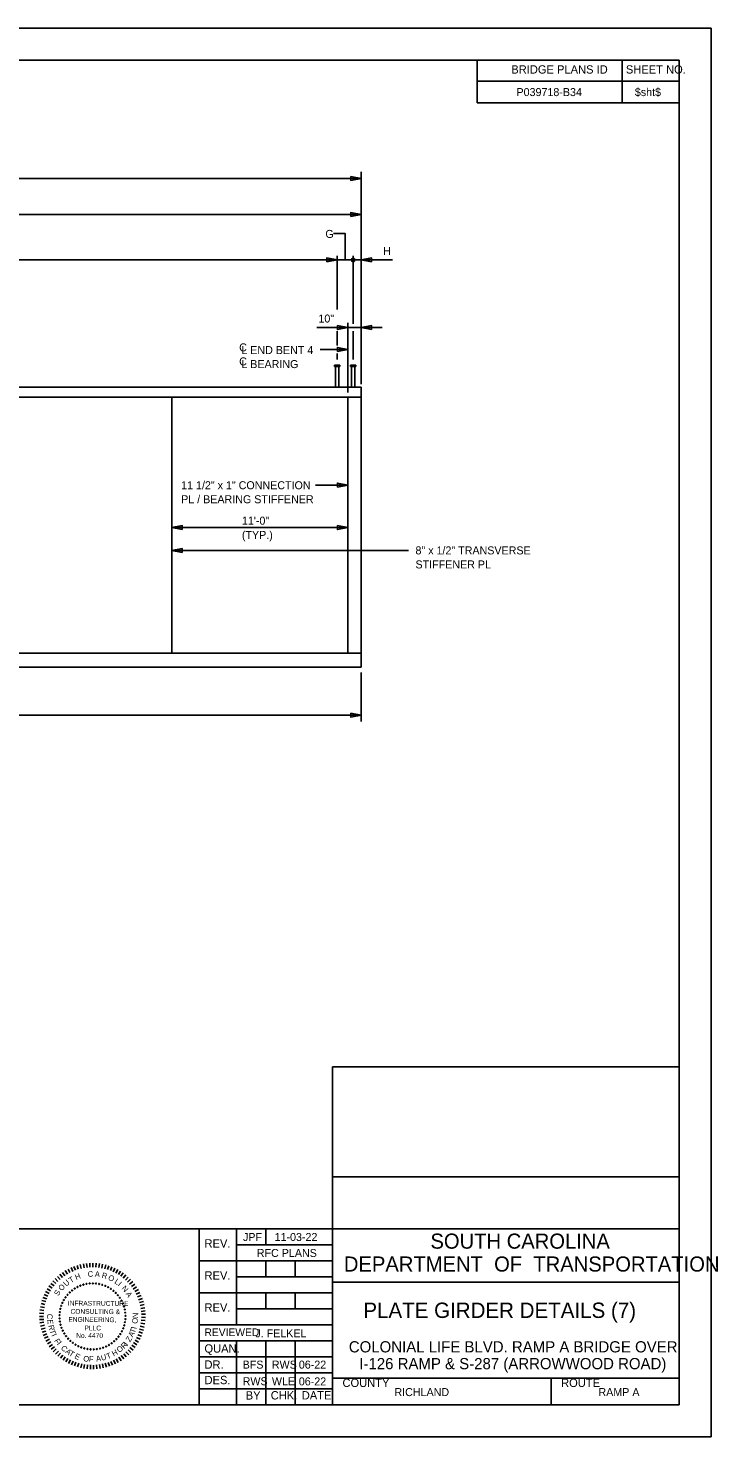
# Model space of a CAD drawing. Extents: x -383 to -161, y -356 to -99.
# Drawn here: x -203.9 to -160.8, y -187.5 to -99.5 of the extents above; entities that cross this region are included whole.
import ezdxf

# ---------------------------------------------------------------- set-up
doc = ezdxf.new("R2010")
doc.units = 0
for name, color, linetype in [('BR_AUTO DIMENSION', 7, 'Continuous'), ('BR_BORDER LINES', 7, 'Continuous'), ('BR_CENTER LINES', 7, 'Continuous'), ('BR_STRUCTURAL STEEL', 7, 'Continuous'), ('BR_TEXT', 7, 'Continuous'), ('Default', 7, 'Continuous'), ('Level 31', 7, 'Continuous')]:
    doc.layers.add(name, color=color, linetype=linetype)

msp = doc.modelspace()

# ---------------------------------------------------------------- linework, layer by layer
at = {"layer": 'BR_AUTO DIMENSION'}
for p, q in [((-278.644, -108.876), (-183.048, -108.876)), ((-183.048, -121.718), (-183.048, -108.463)), ((-278.644, -111.134), (-183.048, -111.134)), ((-184.548, -113.971), (-277.144, -113.971)), ((-184.548, -117.054), (-184.548, -113.71)), ((-181.095, -113.971), (-184.548, -113.971)), ((-183.548, -117.968), (-183.548, -113.71)), ((-185.813, -118.196), (-181.742, -118.196)), ((-184.548, -119.304), (-184.548, -118.423)), ((-183.548, -120.185), (-183.548, -118.423)), ((-183.882, -119.558), (-185.605, -119.558)), ((-184.548, -120.185), (-184.548, -119.822)), ((-183.882, -128.037), (-185.899, -128.037)), ((-194.882, -130.686), (-183.882, -130.686)), ((-194.882, -132.128), (-180.084, -132.128)), ((-183.048, -139.746), (-183.048, -142.798)), ((-278.644, -142.397), (-183.048, -142.397))]:
    msp.add_line(p, q, dxfattribs=at)
for points in [[(-183.698, -108.751), (-183.048, -108.876), (-183.698, -109.001)], [(-183.698, -111.259), (-183.048, -111.134), (-183.698, -111.009)], [(-185.198, -114.096), (-184.548, -113.971), (-185.198, -113.846)], [(-182.398, -114.096), (-183.048, -113.971), (-182.398, -113.846)], [(-184.532, -118.071), (-183.882, -118.196), (-184.532, -118.321)], [(-182.398, -118.321), (-183.048, -118.196), (-182.398, -118.071)], [(-184.532, -119.683), (-183.882, -119.558), (-184.532, -119.433)], [(-184.532, -128.162), (-183.882, -128.037), (-184.532, -127.912)], [(-194.232, -130.811), (-194.882, -130.686), (-194.232, -130.561)], [(-184.532, -130.561), (-183.882, -130.686), (-184.532, -130.811)], [(-194.232, -132.253), (-194.882, -132.128), (-194.232, -132.003)], [(-183.698, -142.272), (-183.048, -142.397), (-183.698, -142.522)]]:
    msp.add_lwpolyline(points, close=True, dxfattribs=at)
msp.add_lwpolyline([(-184.048, -113.971), (-184.048, -112.325), (-184.788, -112.325)], dxfattribs=at)
msp.add_circle((-183.548, -113.971), 0.111, dxfattribs=at)
at = {"layer": 'BR_BORDER LINES'}
for p, q in [((-163.178, -101.489), (-297.843, -101.489)), ((-175.788, -104.156), (-175.788, -101.489)), ((-166.722, -104.156), (-166.722, -101.489)), ((-163.178, -185.489), (-163.178, -101.489)), ((-175.788, -102.808), (-163.178, -102.808)), ((-166.722, -102.808), (-163.178, -102.808)), ((-163.178, -104.156), (-175.788, -104.156)), ((-184.846, -185.489), (-184.846, -164.383)), ((-184.846, -164.383), (-163.178, -164.383)), ((-184.845, -171.242), (-163.178, -171.242)), ((-214.64, -174.489), (-193.18, -174.489)), ((-193.18, -185.489), (-193.18, -174.489)), ((-193.18, -174.489), (-163.178, -174.489)), ((-190.846, -174.489), (-190.846, -180.489)), ((-189.013, -175.489), (-189.013, -174.489)), ((-190.846, -175.489), (-184.846, -175.489)), ((-193.18, -176.489), (-184.846, -176.489)), ((-189.013, -177.489), (-189.013, -176.489)), ((-187.179, -177.489), (-187.179, -176.489)), ((-190.846, -177.489), (-184.846, -177.489)), ((-193.18, -178.489), (-184.846, -178.489)), ((-189.013, -179.489), (-189.013, -178.489)), ((-187.179, -179.489), (-187.179, -178.489)), ((-184.846, -177.822), (-184.846, -177.822)), ((-184.846, -177.823), (-163.178, -177.823)), ((-190.846, -179.489), (-184.846, -179.489)), ((-193.18, -180.489), (-184.846, -180.489)), ((-193.18, -181.489), (-184.846, -181.489)), ((-190.846, -181.489), (-190.846, -185.489)), ((-189.013, -181.489), (-189.013, -185.489)), ((-187.179, -181.489), (-187.179, -185.489)), ((-193.18, -182.489), (-184.846, -182.489)), ((-193.18, -183.489), (-184.846, -183.489)), ((-184.846, -183.823), (-163.178, -183.823)), ((-184.456, -183.823), (-163.178, -183.823)), ((-171.179, -185.489), (-171.179, -183.823)), ((-193.18, -184.489), (-184.846, -184.489)), ((-297.843, -185.489), (-163.178, -185.489))]:
    msp.add_line(p, q, dxfattribs=at)
at = {"layer": 'BR_CENTER LINES'}
msp.add_line((-183.882, -117.887), (-183.882, -122.256), dxfattribs=at)
at = {"layer": 'BR_STRUCTURAL STEEL'}
for p, q in [((-278.644, -121.912), (-183.048, -121.912)), ((-183.048, -121.912), (-183.048, -122.537)), ((-278.644, -122.537), (-183.048, -122.537)), ((-194.882, -122.537), (-194.882, -138.537)), ((-183.882, -122.537), (-183.882, -138.537)), ((-183.048, -122.537), (-183.048, -138.537)), ((-278.644, -138.537), (-183.048, -138.537)), ((-183.048, -138.537), (-183.048, -139.412)), ((-278.644, -139.412), (-183.048, -139.412))]:
    msp.add_line(p, q, dxfattribs=at)
at = {"layer": 'BR_TEXT'}
for p, q in [((-201.001, -176.844), (-200.912, -177.082)), ((-200.81, -176.779), (-200.735, -177.023)), ((-200.615, -176.726), (-200.555, -176.974)), ((-200.417, -176.685), (-200.373, -176.936)), ((-200.217, -176.656), (-200.188, -176.909)), ((-200.016, -176.64), (-200.002, -176.894)), ((-199.814, -176.636), (-199.816, -176.89)), ((-199.612, -176.644), (-199.63, -176.898)), ((-199.411, -176.664), (-199.444, -176.917)), ((-199.212, -176.697), (-199.26, -176.947)), ((-199.015, -176.741), (-199.079, -176.988)), ((-198.821, -176.798), (-198.9, -177.04)), ((-198.631, -176.866), (-198.724, -177.103)), ((-202.321, -177.748), (-202.13, -177.917)), ((-202.182, -177.601), (-202.002, -177.781)), ((-202.035, -177.463), (-201.866, -177.654)), ((-201.879, -177.334), (-201.723, -177.535)), ((-201.716, -177.215), (-201.572, -177.425)), ((-201.546, -177.106), (-201.415, -177.324)), ((-201.37, -177.007), (-201.252, -177.233)), ((-201.188, -176.92), (-201.084, -177.153)), ((-198.446, -176.946), (-198.553, -177.177)), ((-198.265, -177.037), (-198.387, -177.261)), ((-198.091, -177.139), (-198.226, -177.355)), ((-197.923, -177.251), (-198.071, -177.458)), ((-197.762, -177.373), (-197.922, -177.571)), ((-197.609, -177.505), (-197.781, -177.693)), ((-197.464, -177.646), (-197.647, -177.823)), ((-202.867, -178.593), (-202.634, -178.696)), ((-202.779, -178.411), (-202.553, -178.529)), ((-202.679, -178.235), (-202.461, -178.366)), ((-202.57, -178.065), (-202.36, -178.21)), ((-202.45, -177.903), (-202.25, -178.06)), ((-197.329, -177.795), (-197.522, -177.961)), ((-197.202, -177.952), (-197.405, -178.106)), ((-197.086, -178.117), (-197.298, -178.258)), ((-196.979, -178.289), (-197.199, -178.417)), ((-196.883, -178.467), (-197.111, -178.581)), ((-203.104, -179.363), (-202.853, -179.407)), ((-203.063, -179.165), (-202.815, -179.225)), ((-203.009, -178.97), (-202.766, -179.045)), ((-202.944, -178.779), (-202.705, -178.869)), ((-196.799, -178.65), (-197.033, -178.75)), ((-196.725, -178.838), (-196.965, -178.924)), ((-196.664, -179.03), (-196.908, -179.101)), ((-196.614, -179.226), (-196.862, -179.282)), ((-196.576, -179.424), (-196.827, -179.465)), ((-203.156, -179.965), (-202.901, -179.964)), ((-203.151, -179.764), (-202.897, -179.777)), ((-203.149, -180.167), (-202.895, -180.15)), ((-203.134, -179.562), (-202.881, -179.592)), ((-203.129, -180.368), (-202.877, -180.335)), ((-196.57, -180.43), (-196.822, -180.393)), ((-196.55, -179.625), (-196.804, -179.65)), ((-196.547, -180.23), (-196.8, -180.208)), ((-196.537, -179.826), (-196.791, -179.836)), ((-196.535, -180.028), (-196.79, -180.022)), ((-203.097, -180.568), (-202.847, -180.52)), ((-203.053, -180.765), (-202.807, -180.701)), ((-202.997, -180.959), (-202.755, -180.881)), ((-202.93, -181.149), (-202.693, -181.056)), ((-202.851, -181.335), (-202.62, -181.228)), ((-196.784, -181.207), (-197.02, -181.111)), ((-196.713, -181.018), (-196.954, -180.936)), ((-196.653, -180.825), (-196.899, -180.758)), ((-196.606, -180.629), (-196.855, -180.577)), ((-202.761, -181.516), (-202.536, -181.395)), ((-202.66, -181.69), (-202.443, -181.556)), ((-202.548, -181.859), (-202.34, -181.711)), ((-202.426, -182.02), (-202.228, -181.86)), ((-202.295, -182.173), (-202.107, -182.002)), ((-202.155, -182.319), (-201.977, -182.136)), ((-197.438, -182.219), (-197.623, -182.045)), ((-197.304, -182.068), (-197.5, -181.905)), ((-197.179, -181.91), (-197.385, -181.759)), ((-197.065, -181.743), (-197.279, -181.605)), ((-196.96, -181.57), (-197.182, -181.446)), ((-196.867, -181.392), (-197.096, -181.281)), ((-202.006, -182.455), (-201.84, -182.262)), ((-201.849, -182.582), (-201.695, -182.379)), ((-201.685, -182.699), (-201.543, -182.487)), ((-201.513, -182.806), (-201.385, -182.586)), ((-201.336, -182.903), (-201.221, -182.675)), ((-201.153, -182.988), (-201.053, -182.754)), ((-200.965, -183.062), (-200.879, -182.822)), ((-200.773, -183.125), (-200.702, -182.88)), ((-200.577, -183.175), (-200.521, -182.927)), ((-200.379, -183.214), (-200.338, -182.962)), ((-200.179, -183.24), (-200.154, -182.987)), ((-199.978, -183.254), (-199.968, -183)), ((-199.776, -183.256), (-199.781, -183.002)), ((-199.574, -183.246), (-199.595, -182.992)), ((-199.373, -183.223), (-199.41, -182.971)), ((-199.174, -183.188), (-199.226, -182.939)), ((-198.978, -183.142), (-199.045, -182.896)), ((-198.785, -183.083), (-198.867, -182.842)), ((-198.596, -183.012), (-198.692, -182.777)), ((-198.411, -182.93), (-198.522, -182.701)), ((-198.232, -182.837), (-198.356, -182.615)), ((-198.059, -182.734), (-198.196, -182.519)), ((-197.892, -182.62), (-198.042, -182.414)), ((-197.733, -182.495), (-197.895, -182.3)), ((-197.581, -182.362), (-197.756, -182.176))]:
    msp.add_line(p, q, dxfattribs=at)
for centre, start, end in [((-201.408, -178.617), 49.37299, 229.37299), ((-201.408, -178.617), 229.37299, 49.37299), ((-201.27, -178.472), 43.83453, 223.83453), ((-201.27, -178.472), 223.83453, 43.83453), ((-201.12, -178.341), 38.29606, 218.29606), ((-201.12, -178.341), 218.29606, 38.29606), ((-200.957, -178.226), 32.7576, 212.7576), ((-200.957, -178.226), 212.7576, 32.7576), ((-200.785, -178.127), 27.21914, 207.21914), ((-200.785, -178.127), 207.21914, 27.21914), ((-200.603, -178.045), 21.68068, 201.68068), ((-200.603, -178.045), 201.68068, 21.68068), ((-200.414, -177.98), 16.14222, 196.14222), ((-200.414, -177.98), 196.14222, 16.14222), ((-200.22, -177.935), 10.60376, 190.60376), ((-200.22, -177.935), 190.60376, 10.60376), ((-200.023, -177.908), 5.06529, 185.06529), ((-200.023, -177.908), 185.06529, 5.06529), ((-199.824, -177.9), 359.52683, 179.52683), ((-199.824, -177.9), 179.52683, 359.52683), ((-199.625, -177.912), 353.98837, 173.98837), ((-199.625, -177.912), 173.98837, 353.98837), ((-199.428, -177.943), 168.44991, 348.44991), ((-199.428, -177.943), 348.44991, 168.44991), ((-199.235, -177.992), 162.91145, 342.91145), ((-199.235, -177.992), 342.91145, 162.91145), ((-199.047, -178.06), 157.37299, 337.37299), ((-199.047, -178.06), 337.37299, 157.37299), ((-198.867, -178.146), 151.83453, 331.83453), ((-198.867, -178.146), 331.83453, 151.83453), ((-198.697, -178.249), 146.29606, 326.29606), ((-198.697, -178.249), 326.29606, 146.29606), ((-198.537, -178.368), 140.7576, 320.7576), ((-198.537, -178.368), 320.7576, 140.7576), ((-198.389, -178.502), 135.21914, 315.21914), ((-198.389, -178.502), 315.21914, 135.21914), ((-198.255, -178.649), 129.68068, 309.68068), ((-198.255, -178.649), 309.68068, 129.68068), ((-201.854, -179.497), 77.06529, 257.06529), ((-201.854, -179.497), 257.06529, 77.06529), ((-201.8, -179.305), 71.52683, 251.52683), ((-201.8, -179.305), 251.52683, 71.52683), ((-201.727, -179.12), 65.98837, 245.98837), ((-201.727, -179.12), 245.98837, 65.98837), ((-201.637, -178.942), 60.44991, 240.44991), ((-201.637, -178.942), 240.44991, 60.44991), ((-201.53, -178.774), 54.91145, 234.91145), ((-201.53, -178.774), 234.91145, 54.91145), ((-198.135, -178.809), 124.14222, 304.14222), ((-198.135, -178.809), 304.14222, 124.14222), ((-198.032, -178.979), 118.60376, 298.60376), ((-198.032, -178.979), 298.60376, 118.60376), ((-197.945, -179.159), 113.06529, 293.06529), ((-197.945, -179.159), 293.06529, 113.06529), ((-197.876, -179.346), 107.52683, 287.52683), ((-197.876, -179.346), 287.52683, 107.52683), ((-197.826, -179.538), 101.98837, 281.98837), ((-197.826, -179.538), 281.98837, 101.98837), ((-201.906, -179.892), 88.14222, 268.14222), ((-201.904, -180.091), 93.68068, 273.68068), ((-201.89, -179.693), 82.60376, 262.60376), ((-201.882, -180.289), 99.21914, 279.21914), ((-201.906, -179.892), 268.14222, 88.14222), ((-201.904, -180.091), 273.68068, 93.68068), ((-201.89, -179.693), 262.60376, 82.60376), ((-201.882, -180.289), 279.21914, 99.21914), ((-197.815, -180.331), 79.83453, 259.83453), ((-197.795, -179.735), 96.44991, 276.44991), ((-197.815, -180.331), 259.83453, 79.83453), ((-197.789, -180.133), 85.37299, 265.37299), ((-197.782, -179.934), 90.91145, 270.91145), ((-197.795, -179.735), 276.44991, 96.44991), ((-197.789, -180.133), 265.37299, 85.37299), ((-197.782, -179.934), 270.91145, 90.91145), ((-201.841, -180.484), 104.7576, 284.7576), ((-201.841, -180.484), 284.7576, 104.7576), ((-201.781, -180.675), 110.29606, 290.29606), ((-201.781, -180.675), 290.29606, 110.29606), ((-201.703, -180.858), 115.83453, 295.83453), ((-201.703, -180.858), 295.83453, 115.83453), ((-201.608, -181.033), 121.37299, 301.37299), ((-201.608, -181.033), 301.37299, 121.37299), ((-201.497, -181.199), 126.91145, 306.91145), ((-201.497, -181.199), 306.91145, 126.91145), ((-198.219, -181.232), 52.14222, 232.14222), ((-198.219, -181.232), 232.14222, 52.14222), ((-198.104, -181.069), 57.68068, 237.68068), ((-198.104, -181.069), 237.68068, 57.68068), ((-198.005, -180.896), 63.21914, 243.21914), ((-198.005, -180.896), 243.21914, 63.21914), ((-197.924, -180.714), 68.7576, 248.7576), ((-197.924, -180.714), 248.7576, 68.7576), ((-197.86, -180.525), 74.29606, 254.29606), ((-197.86, -180.525), 254.29606, 74.29606), ((-201.37, -181.352), 132.44991, 312.44991), ((-201.37, -181.352), 312.44991, 132.44991), ((-201.228, -181.493), 137.98837, 317.98837), ((-201.228, -181.493), 317.98837, 137.98837), ((-201.074, -181.619), 143.52683, 323.52683), ((-201.074, -181.619), 323.52683, 143.52683), ((-200.909, -181.73), 149.06529, 329.06529), ((-200.909, -181.73), 329.06529, 149.06529), ((-200.733, -181.825), 154.60376, 334.60376), ((-200.733, -181.825), 334.60376, 154.60376), ((-200.549, -181.902), 160.14222, 340.14222), ((-200.549, -181.902), 340.14222, 160.14222), ((-200.359, -181.961), 165.68068, 345.68068), ((-200.359, -181.961), 345.68068, 165.68068), ((-200.164, -182.001), 171.21914, 351.21914), ((-200.164, -182.001), 351.21914, 171.21914), ((-199.965, -182.022), 176.7576, 356.7576), ((-199.965, -182.022), 356.7576, 176.7576), ((-199.766, -182.024), 2.29606, 182.29606), ((-199.766, -182.024), 182.29606, 2.29606), ((-199.568, -182.007), 7.83453, 187.83453), ((-199.568, -182.007), 187.83453, 7.83453), ((-199.372, -181.971), 13.37299, 193.37299), ((-199.372, -181.971), 193.37299, 13.37299), ((-199.18, -181.916), 18.91145, 198.91145), ((-199.18, -181.916), 198.91145, 18.91145), ((-198.995, -181.842), 24.44991, 204.44991), ((-198.995, -181.842), 204.44991, 24.44991), ((-198.817, -181.752), 29.98837, 209.98837), ((-198.817, -181.752), 209.98837, 29.98837), ((-198.649, -181.644), 35.52683, 215.52683), ((-198.649, -181.644), 215.52683, 35.52683), ((-198.493, -181.521), 41.06529, 221.06529), ((-198.493, -181.521), 221.06529, 41.06529), ((-198.349, -181.383), 46.60376, 226.60376), ((-198.349, -181.383), 226.60376, 46.60376)]:
    msp.add_arc(centre, 0.028, start, end, dxfattribs=at)
at = {"layer": 'Default'}
for p, q in [((-184.72, -120.537), (-184.72, -120.631)), ((-184.72, -120.537), (-184.376, -120.537)), ((-184.376, -120.537), (-184.376, -120.631)), ((-183.72, -120.537), (-183.72, -120.631)), ((-183.72, -120.537), (-183.376, -120.537)), ((-183.376, -120.537), (-183.376, -120.631)), ((-184.72, -120.631), (-184.376, -120.631)), ((-184.658, -120.631), (-184.658, -121.912)), ((-184.439, -120.631), (-184.439, -121.912)), ((-183.72, -120.631), (-183.376, -120.631)), ((-183.658, -120.631), (-183.658, -121.912)), ((-183.439, -120.631), (-183.439, -121.912))]:
    msp.add_line(p, q, dxfattribs=at)
at = {"layer": 'Level 31'}
msp.add_line((-174.011, -179.583), (-174.011, -179.583), dxfattribs=at)
msp.add_lwpolyline([(-305.176, -187.489), (-161.176, -187.489), (-161.176, -99.489), (-305.176, -99.489)], close=True, dxfattribs=at)

# ---------------------------------------------------------------- texts
at = {"layer": 'BR_AUTO DIMENSION'}
for s, p in [('G', (-185.284, -112.593)), ('H', (-181.668, -113.652)), ('10"', (-185.72, -117.877)), ('11\'-0"', (-190.503, -130.507)), ('(TYP.)', (-190.504, -131.398))]:
    msp.add_text(s, height=0.5, rotation=360, dxfattribs=at).set_placement(p)
at = {"layer": 'BR_TEXT'}
for s, height, p in [('BRIDGE PLANS ID', 0.52, (-173.663, -102.327)), ('SHEET NO.', 0.52, (-166.499, -102.327)), ('P039718-B34', 0.5, (-173.338, -103.732)), ('$sht$', 0.5, (-165.939, -103.732)), ('JPF', 0.5, (-190.438, -175.257)), ('11-03-22', 0.5, (-188.461, -175.257)), ('SOUTH CAROLINA', 0.94348, (-178.718, -175.735)), ('REV.', 0.52, (-192.841, -175.667)), ('RFC PLANS', 0.5, (-189.572, -176.253)), ('DEPARTMENT  OF  TRANSPORTATION', 0.94348, (-184.129, -177.166)), ('REV.', 0.52, (-192.841, -177.667)), ('REV.', 0.52, (-192.841, -179.667)), ('PLATE GIRDER DETAILS (7)', 0.96, (-182.913, -180.063)), ('REVIEWED', 0.48, (-192.843, -181.195)), ('J. FELKEL', 0.5, (-189.664, -181.272)), ('QUAN.', 0.52, (-192.846, -182.229)), ('COLONIAL LIFE BLVD. RAMP A BRIDGE OVER', 0.7, (-183.82, -182.216)), ('DR.', 0.52, (-192.845, -183.235)), ('BFS', 0.5, (-190.457, -183.228)), ('RWS', 0.5, (-188.632, -183.228)), ('06-22', 0.5, (-186.946, -183.228)), ('I-126 RAMP & S-287 (ARROWWOOD ROAD)', 0.7, (-183.162, -183.266)), ('DES.', 0.52, (-192.841, -184.2)), ('RWS', 0.5, (-190.457, -184.267)), ('WLE', 0.5, (-188.63, -184.267)), ('06-22', 0.5, (-186.946, -184.276)), ('COUNTY', 0.52, (-184.217, -184.376)), ('ROUTE', 0.52, (-170.55, -184.376)), ('BY', 0.52, (-190.265, -185.161)), ('CHK.', 0.52, (-188.701, -185.156)), ('DATE', 0.52, (-186.761, -185.156)), ('RICHLAND', 0.5, (-180.968, -184.944)), ('RAMP A', 0.5, (-168.212, -184.944))]:
    msp.add_text(s, height=height, dxfattribs=at).set_placement(p)
for s, height, rotation, p in [('C', 0.5, 360, (-190.675, -119.681)), ('L END BENT 4', 0.5, 360, (-190.54, -119.848)), ('C', 0.5, 360, (-190.675, -120.556)), ('L BEARING', 0.5, 360, (-190.54, -120.723)), ('11 1/2" x 1" CONNECTION ', 0.5, 360, (-194.303, -128.293)), ('PL / BEARING STIFFENER', 0.5, 360, (-194.303, -129.168)), ('8" x 1/2" TRANSVERSE ', 0.5, 360, (-179.652, -132.364)), ('STIFFENER PL', 0.5, 360, (-179.652, -133.239)), ('U', 0.349, 40.84822, (-201.49, -178.119)), ('T', 0.349, 31.81819, (-201.196, -177.894)), ('H', 0.349, 22.78817, (-200.857, -177.704)), ('C', 0.349, 4.72812, (-200.126, -177.506)), ('A', 0.349, 355.69809, (-199.708, -177.486)), ('R', 0.349, 346.66807, (-199.291, -177.554)), ('O', 0.349, 337.63804, (-198.9, -177.673)), ('L', 0.349, 327.10802, (-198.504, -177.875)), ('S', 0.349, 58.90827, (-201.979, -178.715)), ('O', 0.349, 49.87824, (-201.757, -178.403)), ('I', 0.349, 319.578, (-198.294, -178.026)), ('N', 0.349, 310.54797, (-198.051, -178.23)), ('A', 0.349, 301.51795, (-197.791, -178.559)), ('INFRASTRUCTURE', 0.29909, 359.52683, (-201.385, -179.286)), ('CONSULTING &', 0.29909, 359.52683, (-201.22, -179.8)), ('C', 0.349, 267.02504, (-202.679, -179.795)), ('E', 0.349, 273.02504, (-202.662, -180.161)), ('ENGINEERING,', 0.29909, 359.52683, (-201.354, -180.302)), ('O', 0.349, 83.20849, (-197.038, -180.44)), ('N', 0.349, 89.20849, (-196.993, -180.074)), ('R', 0.349, 279.02504, (-202.61, -180.531)), ('T', 0.349, 285.02504, (-202.541, -180.846)), ('I', 0.349, 293.77127, (-202.422, -181.138)), ('No. 4470', 0.2991, 359.52683, (-200.865, -181.304)), ('PLLC', 0.2991, 359.52683, (-200.347, -180.836)), ('Z', 0.349, 57.39539, (-197.501, -181.594)), ('A', 0.349, 63.39539, (-197.326, -181.288)), ('T', 0.349, 69.39539, (-197.203, -181.047)), ('I', 0.349, 77.90926, (-197.1, -180.777)), ('F', 0.349, 299.77127, (-202.257, -181.482)), ('I', 0.349, 308.52683, (-202.089, -181.698)), ('C', 0.349, 314.52683, (-201.851, -181.978)), ('A', 0.349, 320.52683, (-201.575, -182.213)), ('T', 0.349, 326.52683, (-201.357, -182.366)), ('H', 0.349, 28.52683, (-198.522, -182.478)), ('O', 0.349, 38.52683, (-198.169, -182.254)), ('R', 0.349, 44.52683, (-197.863, -182.014)), ('I', 0.349, 52.33388, (-197.665, -181.825)), ('E', 0.349, 332.52683, (-201.003, -182.558)), ('O', 0.349, 350.52683, (-200.442, -182.753)), ('F', 0.349, 356.52683, (-200.076, -182.79)), ('A', 0.349, 10.52683, (-199.597, -182.796)), ('U', 0.349, 16.52683, (-199.261, -182.742)), ('T', 0.349, 22.52683, (-198.894, -182.645))]:
    msp.add_text(s, height=height, rotation=rotation, dxfattribs=at).set_placement(p)

doc.saveas('drawing.dxf')
